// Mitsubishi GX Works2 project: FX2N PLC与安川G7变频器通讯   PLC: FX2N/FX2NC

PROGRAM MAIN
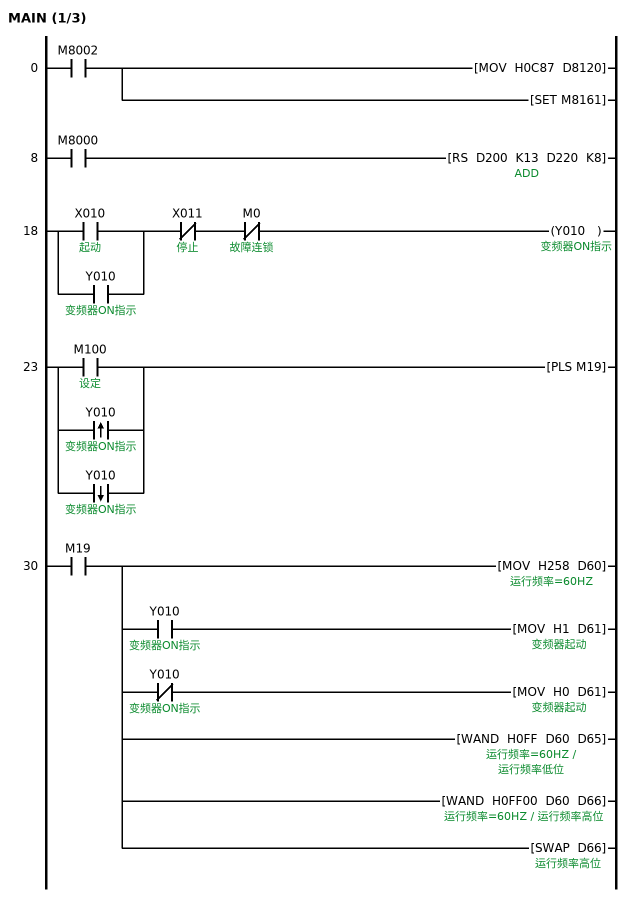
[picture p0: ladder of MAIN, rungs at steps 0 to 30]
0     LD      M8002
      MOV     H0C87 D8120
      SET     M8161
8     LD      M8000
      RS      D200 K13 D220 K8  ; ADD
18    LD      X010  ; 起动
      OR      Y010  ; 变频器ON指示
      ANI     X011  ; 停止
      ANI     M0  ; 故障连锁
      OUT     Y010  ; 变频器ON指示
23    LD      M100  ; 设定
      ORP     Y010  ; 变频器ON指示
      ORF     Y010  ; 变频器ON指示
      PLS     M19
30    LD      M19
      MOV     H258 D60  ; 运行频率=60HZ
      MPS
      AND     Y010  ; 变频器ON指示
      MOV     H1 D61  ; 变频器起动
      MRD
      ANI     Y010  ; 变频器ON指示
      MOV     H0 D61
      MPP
      WAND    H0FF D60 D65  ; 运行频率低位
      WAND    H0FF00 D60 D66  ; 运行频率高位
      SWAP    D66
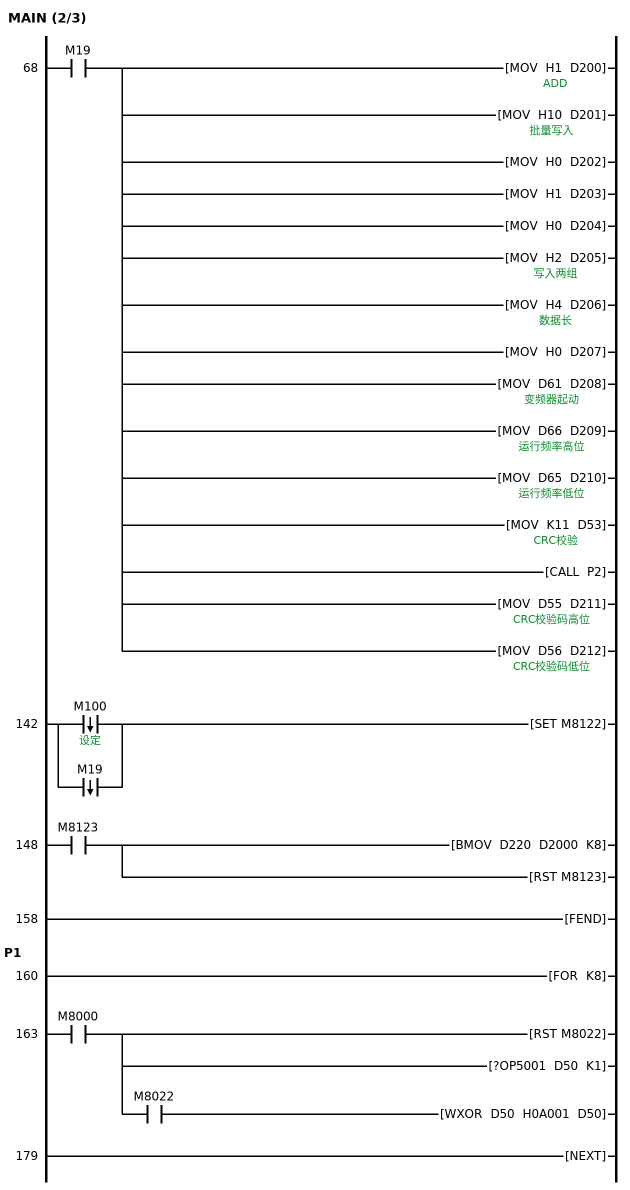
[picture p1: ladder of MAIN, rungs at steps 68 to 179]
68    LD      M19
      MOV     H1 D200
      MOV     H10 D201  ; 批量写入
      MOV     H0 D202
      MOV     H1 D203
      MOV     H0 D204
      MOV     H2 D205  ; 写入两组
      MOV     H4 D206  ; 数据长
      MOV     H0 D207
      MOV     D61 D208
      MOV     D66 D209
      MOV     D65 D210
      MOV     K11 D53  ; CRC校验
      CALL    P2
      MOV     D55 D211  ; CRC校验码高位
      MOV     D56 D212  ; CRC校验码低位
142   LDF     M100  ; 设定
      ORF     M19
      SET     M8122
148   LD      M8123
      BMOV    D220 D2000 K8
      RST     M8123
158   FEND
      P1
160   FOR     K8
163   LD      M8000
      RST     M8022
      ?OP5001 D50 K1
      AND     M8022
      WXOR    D50 H0A001 D50
179   NEXT
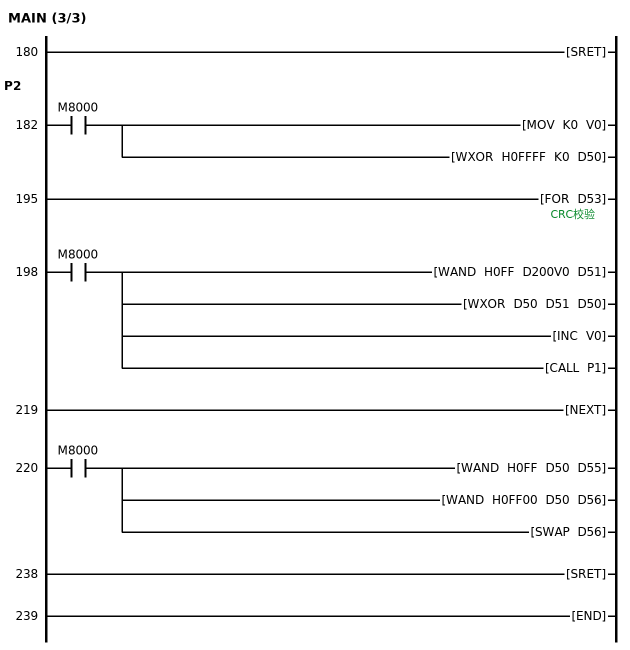
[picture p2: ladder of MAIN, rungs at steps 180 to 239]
180   SRET
      P2
182   LD      M8000
      MOV     K0 V0
      WXOR    H0FFFF K0 D50
195   FOR     D53
198   LD      M8000
      WAND    H0FF D200V0 D51
      WXOR    D50 D51 D50
      INC     V0
      CALL    P1
219   NEXT
220   LD      M8000
      WAND    H0FF D50 D55
      WAND    H0FF00 D50 D56
      SWAP    D56
238   SRET
239   END
END_PROGRAM
